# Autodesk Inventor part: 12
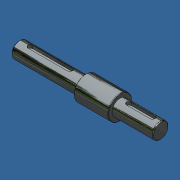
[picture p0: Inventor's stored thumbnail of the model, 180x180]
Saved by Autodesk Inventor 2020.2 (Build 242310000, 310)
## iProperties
Created: 2016-09
Part Number: 12
Material: Steel
Document SubType Name: Modeling
Designer: Mike Taylor
Mass: 548.975 g
Surface Area: 148.624 cm^2
Volume: 69.9331 cm^3
Density: 7.85 g/cm^3
Appearance: Zinc
Translation Standard: STEP AP214IS
FileName: 29_5060_0_1.stp
PreProcessor: ACIS
PostProcessor: Build: 160, Release: 2012 RTM - Date: Tue 03/01/2011
Sent Units: centimeter
Uncertainty: 0.0
Author: Mike Taylor
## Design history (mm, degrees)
node "121"
sketch "Sketch1"
  geometry: L1 (43, 6)-(43, -12) reference; L2 (33, 0)-(30, 0); L3 (33, -6)-(30, -6); A1 r 3 centre (30, -3) between (30, -6) and (30, 0) reference; A2 r 3 centre (33, -3) between (33, 0) and (33, -6); 3 further points
  constraints: 4 end point, 3 point on circle, 3 tangent, 1 centre point, 1 equal radius, 1 horizontal, 1 horizontal alignment, 1 parallel
  dimensions: "d0" = 10 distance from line of A2.centre L1
extrude "Extrusion1" cut sketch "Sketch1" distance "d1" = 10; taper "d2" = 0 deg
sketch "Sketch2"
  geometry: L1 (33, 3)-(0, 3) reference; L2 (0, -3)-(33, -3) reference; C1 r 3 at (3, 0); A1 r 3 centre (0, 0) between (0, 3) and (0, -3) reference; A2 r 3 centre (33, 0) between (33, -3) and (33, 3) reference; 3 further points
  constraints: 1 centre point, 1 equal radius, 1 horizontal alignment
  dimensions: "d3" = 36 dimension on C1 A2
extrude "Extrusion2" join sketch "Sketch2" distance "d4" = 6; taper "d5" = 0 deg
sketch "Sketch3"
  geometry: C1 r 14.5 at (0, 0) reference; C2 r 10 at (0, 0) reference; 1 further point
extrude "Extrusion3" cut sketch "Sketch3" stored distance "d6" = 10; taper "d7" = 0 deg
sketch "Sketch4"
  geometry: C1 r 3 at (0, 0) reference; C2 r 3 at (0, 0) reference; C3 r 1.016 at (0, 0); 1 further point
  constraints: 1 centre point, 1 coincident
extrude "Extrusion4" join sketch "Sketch4" distance "d8" = 20; taper "d9" = 0 deg
sketch "Sketch5"
  geometry: C1 r 9 at (0, 0) reference; 2 further points
  constraints: 1 coincident
hole "Hole1" sketch "Sketch5" at (0, 0) diameter "d10" = 4.917; stored, may be unused: countersink angle "d14" = 90 deg, drill point angle "d16" = 118 deg; dims "d11" = 16, "d12" = 10, "d13" = 3.7, "d15" = 20
node "12"
node "Base1"
